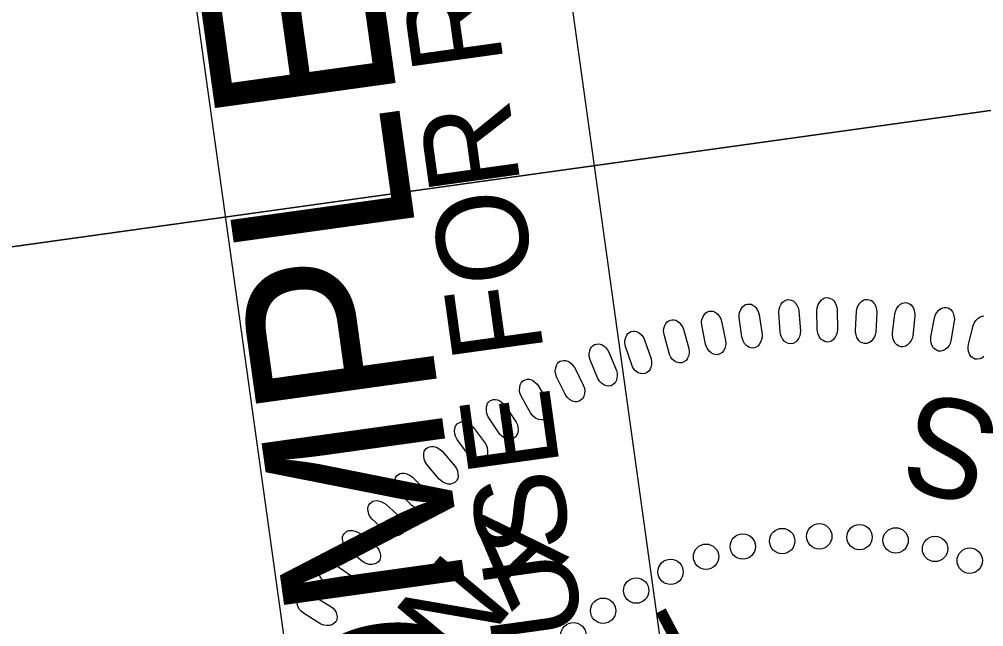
# Model space of a CAD drawing. Extents: x 477151 to 478666, y 496366 to 498184.
# Drawn here: x 477444.6 to 477505.6, y 497904.4 to 497942.7 of the extents above; entities that cross this region are included whole.
import ezdxf

# ---------------------------------------------------------------- set-up
doc = ezdxf.new("R2010")
doc.units = 0
for name, color, linetype in [('Sheet PE Seal Cell', 7, 'Continuous'), ('Sheet Plan CELL', 7, 'Continuous'), ('Sheet Sticker Incomplete CELL', 7, 'Continuous')]:
    doc.layers.add(name, color=color, linetype=linetype)

msp = doc.modelspace()

# ---------------------------------------------------------------- linework, layer by layer
at = {"layer": 'Sheet PE Seal Cell'}
for points in [[(477492.7, 497922.96), (477492.608, 497924.183), (477492.629, 497924.404), (477492.67, 497924.547), (477492.769, 497924.725), (477492.858, 497924.842), (477492.964, 497924.929), (477493.065, 497924.977), (477493.176, 497925.005), (477493.289, 497924.994), (477493.41, 497924.973), (477493.519, 497924.922), (477493.631, 497924.83), (477493.696, 497924.755), (477493.775, 497924.61), (477493.848, 497924.436), (477493.882, 497924.278), (477493.984, 497923.026), (477493.974, 497922.856), (477493.94, 497922.713), (477493.863, 497922.547), (477493.761, 497922.4), (477493.671, 497922.312), (477493.518, 497922.241), (477493.37, 497922.21), (477493.219, 497922.239), (477493.111, 497922.28), (477492.977, 497922.37), (477492.845, 497922.53), (477492.764, 497922.705), (477492.725, 497922.831)], [(477495.04, 497923.117), (477495.025, 497924.344), (477495.06, 497924.563), (477495.11, 497924.704), (477495.22, 497924.876), (477495.316, 497924.986), (477495.427, 497925.067), (477495.531, 497925.108), (477495.644, 497925.129), (477495.756, 497925.111), (477495.876, 497925.082), (477495.981, 497925.024), (477496.087, 497924.925), (477496.147, 497924.847), (477496.217, 497924.698), (477496.279, 497924.519), (477496.303, 497924.36), (477496.326, 497923.103), (477496.306, 497922.933), (477496.262, 497922.793), (477496.175, 497922.633), (477496.065, 497922.491), (477495.968, 497922.41), (477495.812, 497922.349), (477495.663, 497922.327), (477495.513, 497922.365), (477495.407, 497922.414), (477495.279, 497922.511), (477495.158, 497922.68), (477495.088, 497922.859), (477495.057, 497922.988)], [(477497.459, 497923.053), (477497.522, 497924.278), (477497.57, 497924.495), (477497.628, 497924.632), (477497.749, 497924.796), (477497.852, 497924.901), (477497.968, 497924.975), (477498.075, 497925.009), (477498.188, 497925.023), (477498.298, 497924.998), (477498.417, 497924.962), (477498.518, 497924.897), (477498.617, 497924.791), (477498.673, 497924.709), (477498.733, 497924.556), (477498.784, 497924.374), (477498.798, 497924.214), (477498.742, 497922.958), (477498.711, 497922.79), (477498.659, 497922.653), (477498.561, 497922.498), (477498.442, 497922.364), (477498.341, 497922.289), (477498.181, 497922.238), (477498.031, 497922.225), (477497.884, 497922.273), (477497.782, 497922.328), (477497.66, 497922.433), (477497.549, 497922.609), (477497.491, 497922.792), (477497.468, 497922.923)], [(477499.803, 497922.893), (477499.942, 497924.112), (477500.004, 497924.326), (477500.071, 497924.459), (477500.202, 497924.615), (477500.311, 497924.712), (477500.432, 497924.779), (477500.54, 497924.807), (477500.654, 497924.814), (477500.762, 497924.782), (477500.878, 497924.738), (477500.975, 497924.667), (477501.068, 497924.556), (477501.119, 497924.47), (477501.168, 497924.313), (477501.208, 497924.129), (477501.212, 497923.968), (477501.077, 497922.718), (477501.035, 497922.552), (477500.975, 497922.418), (477500.868, 497922.27), (477500.741, 497922.144), (477500.636, 497922.076), (477500.472, 497922.034), (477500.321, 497922.031), (477500.178, 497922.088), (477500.079, 497922.149), (477499.964, 497922.263), (477499.865, 497922.445), (477499.818, 497922.631), (477499.804, 497922.763)], [(477487.99, 497922.187), (477487.746, 497923.389), (477487.739, 497923.611), (477487.762, 497923.759), (477487.838, 497923.947), (477487.911, 497924.074), (477488.006, 497924.174), (477488.1, 497924.234), (477488.206, 497924.276), (477488.32, 497924.279), (477488.443, 497924.274), (477488.557, 497924.236), (477488.68, 497924.159), (477488.754, 497924.093), (477488.851, 497923.96), (477488.945, 497923.796), (477488.998, 497923.644), (477489.256, 497922.414), (477489.268, 497922.243), (477489.252, 497922.097), (477489.196, 497921.923), (477489.114, 497921.764), (477489.035, 497921.667), (477488.893, 497921.577), (477488.75, 497921.527), (477488.596, 497921.537), (477488.483, 497921.565), (477488.339, 497921.637), (477488.188, 497921.779), (477488.086, 497921.942), (477488.031, 497922.063)], [(477490.278, 497922.656), (477490.109, 497923.871), (477490.116, 497924.093), (477490.149, 497924.239), (477490.237, 497924.423), (477490.317, 497924.545), (477490.418, 497924.639), (477490.516, 497924.692), (477490.625, 497924.727), (477490.738, 497924.723), (477490.861, 497924.71), (477490.972, 497924.665), (477491.09, 497924.581), (477491.16, 497924.51), (477491.248, 497924.371), (477491.331, 497924.202), (477491.375, 497924.047), (477491.556, 497922.803), (477491.557, 497922.632), (477491.531, 497922.487), (477491.464, 497922.317), (477491.373, 497922.164), (477491.288, 497922.071), (477491.14, 497921.99), (477490.995, 497921.95), (477490.841, 497921.969), (477490.731, 497922.004), (477490.591, 497922.085), (477490.45, 497922.237), (477490.358, 497922.405), (477490.311, 497922.53)], [(477502.226, 497922.652), (477502.441, 497923.861), (477502.516, 497924.07), (477502.592, 497924.198), (477502.732, 497924.345), (477502.847, 497924.436), (477502.972, 497924.495), (477503.082, 497924.516), (477503.195, 497924.516), (477503.302, 497924.477), (477503.415, 497924.426), (477503.507, 497924.35), (477503.593, 497924.232), (477503.638, 497924.144), (477503.677, 497923.984), (477503.705, 497923.797), (477503.699, 497923.636), (477503.486, 497922.398), (477503.434, 497922.235), (477503.366, 497922.105), (477503.25, 497921.964), (477503.115, 497921.846), (477503.005, 497921.784), (477502.84, 497921.753), (477502.689, 497921.76), (477502.549, 497921.825), (477502.455, 497921.893), (477502.347, 497922.013), (477502.26, 497922.201), (477502.225, 497922.39), (477502.218, 497922.522)], [(477485.682, 497921.62), (477485.363, 497922.804), (477485.341, 497923.026), (477485.355, 497923.174), (477485.419, 497923.367), (477485.484, 497923.499), (477485.572, 497923.605), (477485.662, 497923.671), (477485.765, 497923.718), (477485.879, 497923.729), (477486.002, 497923.731), (477486.119, 497923.701), (477486.246, 497923.631), (477486.324, 497923.57), (477486.428, 497923.443), (477486.533, 497923.285), (477486.597, 497923.137), (477486.931, 497921.926), (477486.953, 497921.756), (477486.946, 497921.61), (477486.901, 497921.433), (477486.829, 497921.268), (477486.756, 497921.166), (477486.621, 497921.067), (477486.481, 497921.009), (477486.327, 497921.009), (477486.213, 497921.03), (477486.064, 497921.093), (477485.904, 497921.225), (477485.793, 497921.381), (477485.73, 497921.499)], [(477483.321, 497920.889), (477482.928, 497922.051), (477482.893, 497922.271), (477482.897, 497922.42), (477482.949, 497922.617), (477483.006, 497922.751), (477483.086, 497922.864), (477483.173, 497922.934), (477483.273, 497922.99), (477483.385, 497923.006), (477483.509, 497923.016), (477483.626, 497922.993), (477483.757, 497922.932), (477483.84, 497922.876), (477483.952, 497922.756), (477484.066, 497922.605), (477484.138, 497922.461), (477484.548, 497921.273), (477484.581, 497921.105), (477484.583, 497920.959), (477484.549, 497920.779), (477484.488, 497920.611), (477484.422, 497920.504), (477484.292, 497920.396), (477484.157, 497920.33), (477484.003, 497920.32), (477483.888, 497920.334), (477483.735, 497920.387), (477483.568, 497920.51), (477483.446, 497920.659), (477483.377, 497920.771)], [(477481.158, 497920.074), (477480.693, 497921.209), (477480.645, 497921.425), (477480.639, 497921.575), (477480.679, 497921.775), (477480.727, 497921.913), (477480.801, 497922.029), (477480.882, 497922.105), (477480.978, 497922.167), (477481.09, 497922.191), (477481.212, 497922.208), (477481.331, 497922.193), (477481.466, 497922.14), (477481.552, 497922.089), (477481.67, 497921.976), (477481.794, 497921.833), (477481.875, 497921.694), (477482.359, 497920.534), (477482.403, 497920.369), (477482.414, 497920.222), (477482.392, 497920.041), (477482.341, 497919.869), (477482.282, 497919.758), (477482.159, 497919.644), (477482.028, 497919.568), (477481.875, 497919.549), (477481.759, 497919.555), (477481.604, 497919.599), (477481.429, 497919.71), (477481.298, 497919.851), (477481.221, 497919.96)], [(477479.109, 497919.036), (477478.573, 497920.14), (477478.511, 497920.354), (477478.496, 497920.502), (477478.523, 497920.704), (477478.562, 497920.845), (477478.629, 497920.966), (477478.705, 497921.047), (477478.798, 497921.114), (477478.907, 497921.145), (477479.028, 497921.17), (477479.148, 497921.162), (477479.286, 497921.118), (477479.374, 497921.073), (477479.501, 497920.967), (477479.633, 497920.832), (477479.723, 497920.698), (477480.279, 497919.571), (477480.332, 497919.409), (477480.352, 497919.264), (477480.342, 497919.082), (477480.302, 497918.907), (477480.249, 497918.792), (477480.134, 497918.669), (477480.008, 497918.587), (477479.856, 497918.557), (477479.741, 497918.557), (477479.582, 497918.591), (477479.401, 497918.69), (477479.262, 497918.823), (477479.179, 497918.926)], [(477476.937, 497917.852), (477476.333, 497918.919), (477476.258, 497919.129), (477476.234, 497919.276), (477476.248, 497919.478), (477476.279, 497919.622), (477476.337, 497919.747), (477476.408, 497919.833), (477476.496, 497919.906), (477476.604, 497919.943), (477476.723, 497919.976), (477476.843, 497919.976), (477476.983, 497919.94), (477477.075, 497919.901), (477477.207, 497919.803), (477477.348, 497919.677), (477477.445, 497919.549), (477478.071, 497918.459), (477478.135, 497918.3), (477478.164, 497918.157), (477478.165, 497917.974), (477478.136, 497917.797), (477478.091, 497917.679), (477477.983, 497917.55), (477477.863, 497917.459), (477477.714, 497917.42), (477477.598, 497917.412), (477477.438, 497917.436), (477477.251, 497917.525), (477477.103, 497917.648), (477477.014, 497917.747)], [(477474.931, 497916.584), (477474.261, 497917.611), (477474.173, 497917.815), (477474.14, 497917.961), (477474.142, 497918.164), (477474.164, 497918.309), (477474.214, 497918.438), (477474.279, 497918.528), (477474.363, 497918.606), (477474.468, 497918.65), (477474.584, 497918.69), (477474.704, 497918.698), (477474.846, 497918.671), (477474.94, 497918.637), (477475.079, 497918.548), (477475.226, 497918.43), (477475.332, 497918.309), (477476.025, 497917.261), (477476.098, 497917.106), (477476.137, 497916.965), (477476.149, 497916.783), (477476.131, 497916.604), (477476.094, 497916.484), (477475.995, 497916.348), (477475.88, 497916.25), (477475.734, 497916.202), (477475.618, 497916.187), (477475.457, 497916.2), (477475.265, 497916.277), (477475.11, 497916.391), (477475.015, 497916.484)], [(477473.021, 497915.2), (477472.288, 497916.183), (477472.187, 497916.382), (477472.145, 497916.524), (477472.133, 497916.728), (477472.146, 497916.874), (477472.188, 497917.005), (477472.249, 497917.099), (477472.326, 497917.182), (477472.428, 497917.233), (477472.542, 497917.281), (477472.661, 497917.296), (477472.805, 497917.278), (477472.9, 497917.25), (477473.044, 497917.17), (477473.199, 497917.062), (477473.313, 497916.947), (477474.069, 497915.944), (477474.153, 497915.795), (477474.2, 497915.656), (477474.223, 497915.475), (477474.217, 497915.296), (477474.187, 497915.173), (477474.097, 497915.032), (477473.989, 497914.926), (477473.846, 497914.869), (477473.732, 497914.846), (477473.57, 497914.85), (477473.373, 497914.915), (477473.212, 497915.019), (477473.11, 497915.105)], [(477471.165, 497913.668), (477470.371, 497914.604), (477470.257, 497914.796), (477470.207, 497914.936), (477470.182, 497915.137), (477470.186, 497915.284), (477470.22, 497915.417), (477470.274, 497915.516), (477470.346, 497915.603), (477470.445, 497915.661), (477470.556, 497915.715), (477470.674, 497915.737), (477470.819, 497915.729), (477470.916, 497915.707), (477471.064, 497915.636), (477471.225, 497915.538), (477471.346, 497915.431), (477472.164, 497914.478), (477472.256, 497914.334), (477472.312, 497914.198), (477472.347, 497914.018), (477472.352, 497913.839), (477472.33, 497913.715), (477472.249, 497913.568), (477472.148, 497913.457), (477472.008, 497913.39), (477471.896, 497913.361), (477471.734, 497913.354), (477471.534, 497913.406), (477471.366, 497913.5), (477471.259, 497913.579)], [(477469.43, 497912.013), (477468.58, 497912.897), (477468.454, 497913.081), (477468.395, 497913.217), (477468.358, 497913.418), (477468.352, 497913.564), (477468.378, 497913.699), (477468.425, 497913.8), (477468.492, 497913.893), (477468.587, 497913.956), (477468.694, 497914.017), (477468.811, 497914.047), (477468.955, 497914.047), (477469.054, 497914.032), (477469.206, 497913.97), (477469.374, 497913.883), (477469.5, 497913.783), (477470.377, 497912.883), (477470.478, 497912.745), (477470.543, 497912.613), (477470.589, 497912.437), (477470.605, 497912.258), (477470.59, 497912.133), (477470.519, 497911.981), (477470.425, 497911.863), (477470.29, 497911.788), (477470.18, 497911.752), (477470.019, 497911.735), (477469.815, 497911.774), (477469.642, 497911.857), (477469.53, 497911.93)], [(477467.826, 497910.315), (477466.922, 497911.144), (477466.785, 497911.32), (477466.717, 497911.453), (477466.668, 497911.65), (477466.653, 497911.796), (477466.67, 497911.932), (477466.711, 497912.036), (477466.772, 497912.133), (477466.863, 497912.202), (477466.966, 497912.27), (477467.081, 497912.307), (477467.225, 497912.316), (477467.324, 497912.307), (477467.48, 497912.255), (477467.652, 497912.178), (477467.785, 497912.087), (477468.717, 497911.243), (477468.827, 497911.112), (477468.899, 497910.985), (477468.956, 497910.811), (477468.984, 497910.634), (477468.977, 497910.508), (477468.915, 497910.352), (477468.828, 497910.228), (477468.698, 497910.145), (477468.591, 497910.102), (477468.431, 497910.075), (477468.226, 497910.102), (477468.048, 497910.173), (477467.932, 497910.239)], [(477466.319, 497908.478), (477465.364, 497909.248), (477465.217, 497909.415), (477465.141, 497909.544), (477465.079, 497909.737), (477465.055, 497909.881), (477465.063, 497910.019), (477465.098, 497910.126), (477465.153, 497910.226), (477465.239, 497910.3), (477465.337, 497910.375), (477465.449, 497910.418), (477465.593, 497910.437), (477465.693, 497910.433), (477465.851, 497910.392), (477466.028, 497910.326), (477466.167, 497910.243), (477467.149, 497909.46), (477467.267, 497909.336), (477467.348, 497909.213), (477467.415, 497909.044), (477467.454, 497908.868), (477467.455, 497908.742), (477467.403, 497908.583), (477467.324, 497908.454), (477467.2, 497908.363), (477467.095, 497908.313), (477466.938, 497908.276), (477466.731, 497908.29), (477466.548, 497908.35), (477466.429, 497908.409)], [(477464.882, 497906.517), (477463.881, 497907.226), (477463.723, 497907.383), (477463.639, 497907.506), (477463.566, 497907.696), (477463.532, 497907.839), (477463.532, 497907.976), (477463.56, 497908.085), (477463.609, 497908.188), (477463.689, 497908.268), (477463.783, 497908.348), (477463.892, 497908.399), (477464.034, 497908.427), (477464.134, 497908.43), (477464.295, 497908.398), (477464.476, 497908.343), (477464.619, 497908.269), (477465.649, 497907.549), (477465.774, 497907.433), (477465.862, 497907.315), (477465.941, 497907.15), (477465.99, 497906.978), (477465.999, 497906.852), (477465.957, 497906.689), (477465.887, 497906.556), (477465.768, 497906.458), (477465.667, 497906.401), (477465.512, 497906.355), (477465.305, 497906.355), (477465.12, 497906.404), (477464.996, 497906.455)], [(477463.627, 497904.554), (477462.583, 497905.198), (477462.416, 497905.345), (477462.324, 497905.463), (477462.239, 497905.647), (477462.197, 497905.788), (477462.188, 497905.925), (477462.209, 497906.035), (477462.251, 497906.141), (477462.326, 497906.226), (477462.415, 497906.312), (477462.521, 497906.369), (477462.661, 497906.406), (477462.76, 497906.415), (477462.923, 497906.393), (477463.107, 497906.35), (477463.254, 497906.286), (477464.327, 497905.632), (477464.46, 497905.524), (477464.555, 497905.412), (477464.644, 497905.252), (477464.704, 497905.083), (477464.721, 497904.958), (477464.689, 497904.793), (477464.627, 497904.656), (477464.515, 497904.549), (477464.418, 497904.487), (477464.266, 497904.431), (477464.059, 497904.419), (477463.87, 497904.456), (477463.745, 497904.498)]]:
    msp.add_lwpolyline(points, close=True, dxfattribs=at)
msp.add_lwpolyline([(477505.571, 497921.422), (477505.429, 497921.312), (477505.316, 497921.257), (477505.149, 497921.237), (477504.999, 497921.253), (477504.863, 497921.327), (477504.774, 497921.4), (477504.673, 497921.527), (477504.598, 497921.72), (477504.575, 497921.911), (477504.577, 497922.043), (477504.593, 497922.173), (477504.883, 497923.365), (477504.971, 497923.569), (477505.055, 497923.692), (477505.205, 497923.831), (477505.325, 497923.914), (477505.453, 497923.965), (477505.564, 497923.979)], dxfattribs=at)
for centre in [(477495.172, 497910.058), (477497.713, 497910.008), (477490.341, 497909.416), (477492.827, 497909.761), (477499.994, 497909.802), (477488.017, 497908.772), (477502.482, 497909.264), (477504.676, 497908.523), (477485.777, 497907.818), (477483.608, 497906.633), (477481.515, 497905.36), (477479.638, 497903.813)]:
    msp.add_circle(centre, 0.801, dxfattribs=at)
at = {"layer": 'Sheet Plan CELL'}
msp.add_line((477425.234, 497925.712), (477536.622, 497941.225), dxfattribs=at)
for points in [[(477425.234, 497925.712), (477411.44, 498024.743), (477522.877, 498040.264), (477536.673, 497941.22)], [(477439.025, 497826.616), (477425.234, 497925.712), (477536.673, 497941.22), (477550.437, 497842.134)]]:
    msp.add_lwpolyline(points, close=True, dxfattribs=at)
at = {"layer": 'Sheet Sticker Incomplete CELL'}
msp.add_lwpolyline([(477491.078, 497860.666), (477467.803, 497857.427), (477447.541, 498003.024), (477470.816, 498006.263)], close=True, dxfattribs=at)

# ---------------------------------------------------------------- texts
at = {"layer": 'Sheet PE Seal Cell'}
for s, height, rotation, p in [('S', 6.236, 165.25216, (477506.896, 497917.903)), ('A', 5.669, 43.5955, (477475.747, 497905.276)), ('N', 5.669, 50.08486, (477472.46, 497901.467)), ('L', 5.669, 27.75354, (477486.932, 497899.875))]:
    msp.add_text(s, height=height, rotation=rotation, dxfattribs=at).set_placement(p)
at = {"layer": 'Sheet Sticker Incomplete CELL'}
for s, height, p in [('INCOMPLETE PLANS', 11.52, (477478.256, 497867.918)), ('DO NOT USE FOR R/W ACQUISITION', 5.76, (477484.692, 497872.095))]:
    msp.add_text(s, height=height, rotation=97.92268, dxfattribs=at).set_placement(p)

doc.saveas('drawing.dxf')
